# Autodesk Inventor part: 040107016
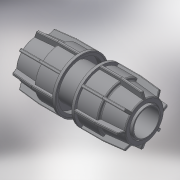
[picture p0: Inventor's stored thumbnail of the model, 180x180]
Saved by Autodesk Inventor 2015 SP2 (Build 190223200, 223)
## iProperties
Created: 2017-08
Part Number: 040107016
Material: Generic
Description: PLASSON IRRIFIT COUPLER 16-16
Document SubType Name: Modeling
Designer: KIM
Density: 1 g/cm^3
Appearance: Default
Author: KIM
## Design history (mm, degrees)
derived "040107.ipt"
feature "Solid1::040107.ipt"
tag "TaggingFeature1"
body "Solid1"
other parameters: "d5" = 30.7, "d6" = 15.84, "d10" = 34, "d22" = 22.4, "d24" = 1.656, "d25" = 30.6, "d26" = 27.2, "d31" = 0.64, "d49" = 1.7, "d50" = 0, "d58" = 0.32, "d61" = 360 deg, "d77" = 16, "d78" = 5 deg, "d80" = 17.6, "d81" = 36, "d82" = 2.16, "d84" = 5 deg, "d85" = 70 deg, "d86" = 32.3, "d87" = 0.36, "d88" = 0, "d89" = 28.9, "d90" = 3.6, "d91" = 0, "d93" = 180 deg, "d_" = 16, "E_" = 34, "H_" = 72, "l_nut" = 30.7
